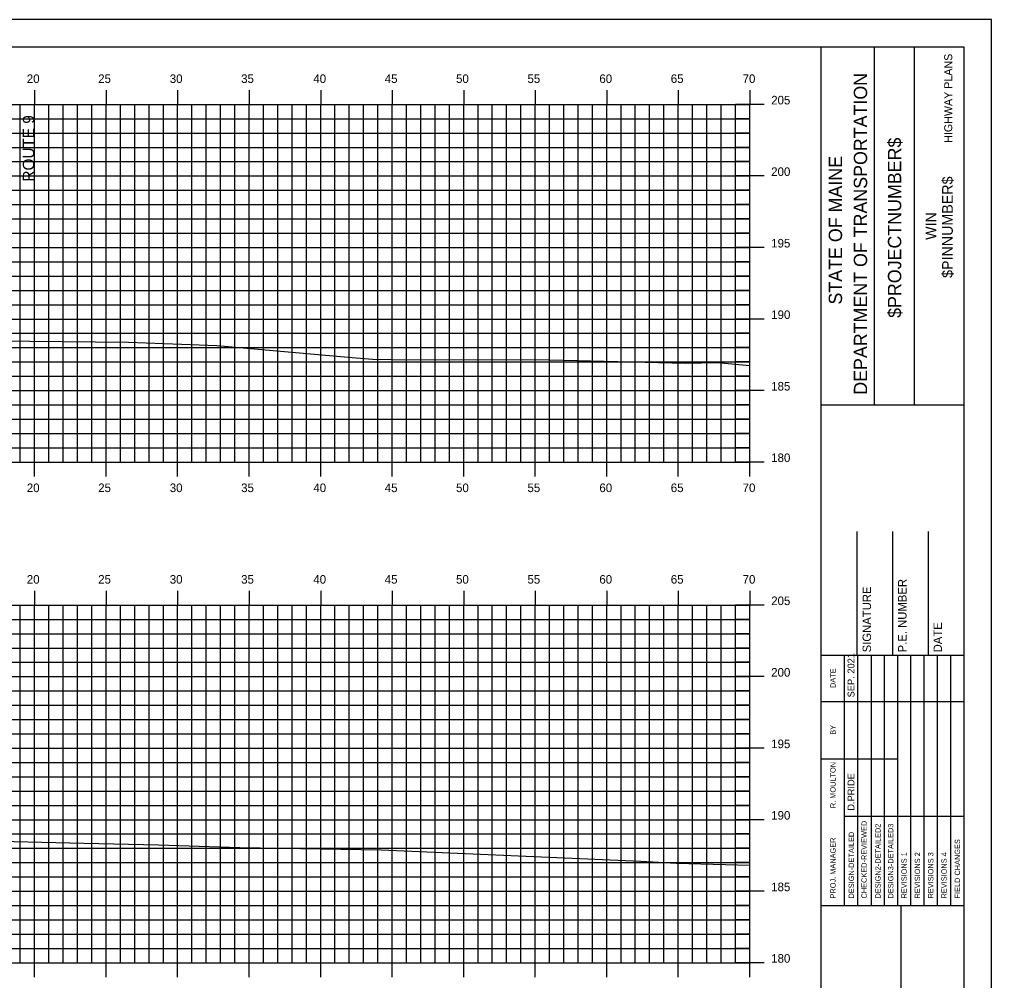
# Model space of a CAD drawing. Extents: x 1723764 to 1723936, y 458501 to 458611.
# Drawn here: x 1723866.5 to 1723934.4, y 458544 to 458611.2 of the extents above; entities that cross this region are included whole.
import ezdxf

# ---------------------------------------------------------------- set-up
doc = ezdxf.new("R2010")
doc.units = 0
for name, color, linetype in [('ANNOTATION', 7, 'Continuous'), ('BORDER', 7, 'Continuous'), ('H_V ANNOTATION', 7, 'Continuous'), ('HIGHWAY_TITLE', 7, 'Continuous'), ('MAJOR', 7, 'Continuous'), ('MINOR', 7, 'Continuous'), ('PLOT BOUNDARY', 7, 'Continuous'), ('S_Roadway_Centerline', 7, 'Continuous')]:
    doc.layers.add(name, color=color, linetype=linetype)

msp = doc.modelspace()

# ---------------------------------------------------------------- linework, layer by layer
at = {"layer": 'BORDER'}
for p, q in [((1723922.542, 458504.254), (1723922.542, 458609.254)), ((1723926.271, 458584.251), (1723926.271, 458609.251)), ((1723929.066, 458584.251), (1723929.066, 458609.251)), ((1723922.543, 458584.248), (1723932.542, 458584.248)), ((1723925.042, 458566.757), (1723925.042, 458575.405)), ((1723927.542, 458566.757), (1723927.542, 458575.405)), ((1723930.042, 458566.757), (1723930.042, 458575.405)), ((1723922.542, 458566.757), (1723932.542, 458566.757)), ((1723922.542, 458549.257), (1723932.542, 458549.257)), ((1723928.133, 458514.257), (1723928.133, 458549.257))]:
    msp.add_line(p, q, dxfattribs=at)
msp.add_lwpolyline([(1723772.542, 458504.254), (1723932.542, 458504.254), (1723932.542, 458609.254), (1723772.542, 458609.254)], close=True, dxfattribs=at)
for points in [[(1723924.157, 458563.507), (1723924.157, 458566.757)], [(1723925.09, 458549.26), (1723925.09, 458566.757)], [(1723926.021, 458566.757), (1723926.021, 458549.26)], [(1723926.953, 458549.26), (1723926.953, 458566.757)], [(1723927.885, 458549.26), (1723927.885, 458566.757)], [(1723928.816, 458549.26), (1723928.816, 458566.757)], [(1723929.748, 458549.26), (1723929.748, 458566.757)], [(1723930.68, 458549.26), (1723930.68, 458566.757)], [(1723931.611, 458549.26), (1723931.611, 458566.757)], [(1723924.158, 458549.26), (1723924.158, 458566.051)], [(1723922.542, 458563.507), (1723932.542, 458563.507)], [(1723922.542, 458559.507), (1723924.158, 458559.507)], [(1723924.157, 458559.507), (1723927.884, 458559.507)], [(1723924.157, 458555.507), (1723932.542, 458555.507)]]:
    msp.add_lwpolyline(points, dxfattribs=at)
at = {"layer": 'MAJOR'}
for p, q in [((1723867.542, 458606.256), (1723867.542, 458605.254)), ((1723872.542, 458606.256), (1723872.542, 458605.254)), ((1723877.542, 458606.256), (1723877.542, 458605.254)), ((1723882.542, 458606.256), (1723882.542, 458605.254)), ((1723887.542, 458606.256), (1723887.542, 458605.254)), ((1723892.542, 458606.256), (1723892.542, 458605.254)), ((1723897.542, 458606.256), (1723897.542, 458605.254)), ((1723902.542, 458606.256), (1723902.542, 458605.254)), ((1723907.542, 458606.256), (1723907.542, 458605.254)), ((1723912.542, 458606.256), (1723912.542, 458605.254)), ((1723917.542, 458606.256), (1723917.542, 458605.254)), ((1723777.542, 458605.254), (1723917.542, 458605.254)), ((1723777.542, 458605.254), (1723917.542, 458605.254)), ((1723867.542, 458580.254), (1723867.542, 458605.254)), ((1723872.542, 458580.254), (1723872.542, 458605.254)), ((1723877.542, 458580.254), (1723877.542, 458605.254)), ((1723882.542, 458580.254), (1723882.542, 458605.254)), ((1723887.542, 458580.254), (1723887.542, 458605.254)), ((1723892.542, 458580.254), (1723892.542, 458605.254)), ((1723897.542, 458580.254), (1723897.542, 458605.254)), ((1723902.542, 458580.254), (1723902.542, 458605.254)), ((1723907.542, 458580.254), (1723907.542, 458605.254)), ((1723912.542, 458580.254), (1723912.542, 458605.254)), ((1723918.544, 458605.254), (1723916.54, 458605.254)), ((1723917.542, 458580.254), (1723917.542, 458605.254)), ((1723917.542, 458580.254), (1723917.542, 458605.254)), ((1723777.542, 458600.254), (1723917.542, 458600.254)), ((1723918.544, 458600.254), (1723916.54, 458600.254)), ((1723777.542, 458595.254), (1723917.542, 458595.254)), ((1723918.544, 458595.254), (1723916.54, 458595.254)), ((1723777.542, 458590.254), (1723917.542, 458590.254)), ((1723918.544, 458590.254), (1723916.54, 458590.254)), ((1723777.542, 458585.254), (1723917.542, 458585.254)), ((1723918.544, 458585.254), (1723916.54, 458585.254)), ((1723777.542, 458580.254), (1723917.542, 458580.254)), ((1723777.542, 458580.254), (1723917.542, 458580.254)), ((1723867.542, 458579.252), (1723867.542, 458580.254)), ((1723872.542, 458579.252), (1723872.542, 458580.254)), ((1723877.542, 458579.252), (1723877.542, 458580.254)), ((1723882.542, 458579.252), (1723882.542, 458580.254)), ((1723887.542, 458579.252), (1723887.542, 458580.254)), ((1723892.542, 458579.252), (1723892.542, 458580.254)), ((1723897.542, 458579.252), (1723897.542, 458580.254)), ((1723902.542, 458579.252), (1723902.542, 458580.254)), ((1723907.542, 458579.252), (1723907.542, 458580.254)), ((1723912.542, 458579.252), (1723912.542, 458580.254)), ((1723918.544, 458580.254), (1723916.54, 458580.254)), ((1723917.542, 458579.252), (1723917.542, 458580.254)), ((1723867.542, 458571.256), (1723867.542, 458570.254)), ((1723872.542, 458571.256), (1723872.542, 458570.254)), ((1723877.542, 458571.256), (1723877.542, 458570.254)), ((1723882.542, 458571.256), (1723882.542, 458570.254)), ((1723887.542, 458571.256), (1723887.542, 458570.254)), ((1723892.542, 458571.256), (1723892.542, 458570.254)), ((1723897.542, 458571.256), (1723897.542, 458570.254)), ((1723902.542, 458571.256), (1723902.542, 458570.254)), ((1723907.542, 458571.256), (1723907.542, 458570.254)), ((1723912.542, 458571.256), (1723912.542, 458570.254)), ((1723917.542, 458571.256), (1723917.542, 458570.254)), ((1723777.542, 458570.254), (1723917.542, 458570.254)), ((1723777.542, 458570.254), (1723917.542, 458570.254)), ((1723867.542, 458545.254), (1723867.542, 458570.254)), ((1723872.542, 458545.254), (1723872.542, 458570.254)), ((1723877.542, 458545.254), (1723877.542, 458570.254)), ((1723882.542, 458545.254), (1723882.542, 458570.254)), ((1723887.542, 458545.254), (1723887.542, 458570.254)), ((1723892.542, 458545.254), (1723892.542, 458570.254)), ((1723897.542, 458545.254), (1723897.542, 458570.254)), ((1723902.542, 458545.254), (1723902.542, 458570.254)), ((1723907.542, 458545.254), (1723907.542, 458570.254)), ((1723912.542, 458545.254), (1723912.542, 458570.254)), ((1723918.544, 458570.254), (1723916.54, 458570.254)), ((1723917.542, 458545.254), (1723917.542, 458570.254)), ((1723917.542, 458545.254), (1723917.542, 458570.254)), ((1723777.542, 458565.254), (1723917.542, 458565.254)), ((1723918.544, 458565.254), (1723916.54, 458565.254)), ((1723777.542, 458560.254), (1723917.542, 458560.254)), ((1723918.544, 458560.254), (1723916.54, 458560.254)), ((1723777.542, 458555.254), (1723917.542, 458555.254)), ((1723918.544, 458555.254), (1723916.54, 458555.254)), ((1723777.542, 458550.254), (1723917.542, 458550.254)), ((1723918.544, 458550.254), (1723916.54, 458550.254)), ((1723777.542, 458545.254), (1723917.542, 458545.254)), ((1723777.542, 458545.254), (1723917.542, 458545.254)), ((1723867.542, 458544.252), (1723867.542, 458545.254)), ((1723872.542, 458544.252), (1723872.542, 458545.254)), ((1723877.542, 458544.252), (1723877.542, 458545.254)), ((1723882.542, 458544.252), (1723882.542, 458545.254)), ((1723887.542, 458544.252), (1723887.542, 458545.254)), ((1723892.542, 458544.252), (1723892.542, 458545.254)), ((1723897.542, 458544.252), (1723897.542, 458545.254)), ((1723902.542, 458544.252), (1723902.542, 458545.254)), ((1723907.542, 458544.252), (1723907.542, 458545.254)), ((1723912.542, 458544.252), (1723912.542, 458545.254)), ((1723918.544, 458545.254), (1723916.54, 458545.254)), ((1723917.542, 458544.252), (1723917.542, 458545.254))]:
    msp.add_line(p, q, dxfattribs=at)
at = {"layer": 'MINOR'}
for p, q in [((1723866.542, 458580.254), (1723866.542, 458605.254)), ((1723868.542, 458580.254), (1723868.542, 458605.254)), ((1723869.542, 458580.254), (1723869.542, 458605.254)), ((1723870.542, 458580.254), (1723870.542, 458605.254)), ((1723871.542, 458580.254), (1723871.542, 458605.254)), ((1723873.542, 458580.254), (1723873.542, 458605.254)), ((1723874.542, 458580.254), (1723874.542, 458605.254)), ((1723875.542, 458580.254), (1723875.542, 458605.254)), ((1723876.542, 458580.254), (1723876.542, 458605.254)), ((1723878.542, 458580.254), (1723878.542, 458605.254)), ((1723879.542, 458580.254), (1723879.542, 458605.254)), ((1723880.542, 458580.254), (1723880.542, 458605.254)), ((1723881.542, 458580.254), (1723881.542, 458605.254)), ((1723883.542, 458580.254), (1723883.542, 458605.254)), ((1723884.542, 458580.254), (1723884.542, 458605.254)), ((1723885.542, 458580.254), (1723885.542, 458605.254)), ((1723886.542, 458580.254), (1723886.542, 458605.254)), ((1723888.542, 458580.254), (1723888.542, 458605.254)), ((1723889.542, 458580.254), (1723889.542, 458605.254)), ((1723890.542, 458580.254), (1723890.542, 458605.254)), ((1723891.542, 458580.254), (1723891.542, 458605.254)), ((1723893.542, 458580.254), (1723893.542, 458605.254)), ((1723894.542, 458580.254), (1723894.542, 458605.254)), ((1723895.542, 458580.254), (1723895.542, 458605.254)), ((1723896.542, 458580.254), (1723896.542, 458605.254)), ((1723898.542, 458580.254), (1723898.542, 458605.254)), ((1723899.542, 458580.254), (1723899.542, 458605.254)), ((1723900.542, 458580.254), (1723900.542, 458605.254)), ((1723901.542, 458580.254), (1723901.542, 458605.254)), ((1723903.542, 458580.254), (1723903.542, 458605.254)), ((1723904.542, 458580.254), (1723904.542, 458605.254)), ((1723905.542, 458580.254), (1723905.542, 458605.254)), ((1723906.542, 458580.254), (1723906.542, 458605.254)), ((1723908.542, 458580.254), (1723908.542, 458605.254)), ((1723909.542, 458580.254), (1723909.542, 458605.254)), ((1723910.542, 458580.254), (1723910.542, 458605.254)), ((1723911.542, 458580.254), (1723911.542, 458605.254)), ((1723913.542, 458580.254), (1723913.542, 458605.254)), ((1723914.542, 458580.254), (1723914.542, 458605.254)), ((1723915.542, 458580.254), (1723915.542, 458605.254)), ((1723916.542, 458580.254), (1723916.542, 458605.254)), ((1723777.542, 458604.254), (1723917.542, 458604.254)), ((1723917.542, 458604.254), (1723916.54, 458604.254)), ((1723777.542, 458603.254), (1723917.542, 458603.254)), ((1723917.542, 458603.254), (1723916.54, 458603.254)), ((1723777.542, 458602.254), (1723917.542, 458602.254)), ((1723917.542, 458602.254), (1723916.54, 458602.254)), ((1723777.542, 458601.254), (1723917.542, 458601.254)), ((1723917.542, 458601.254), (1723916.54, 458601.254)), ((1723777.542, 458599.254), (1723917.542, 458599.254)), ((1723917.542, 458599.254), (1723916.54, 458599.254)), ((1723777.542, 458598.254), (1723917.542, 458598.254)), ((1723917.542, 458598.254), (1723916.54, 458598.254)), ((1723777.542, 458597.254), (1723917.542, 458597.254)), ((1723917.542, 458597.254), (1723916.54, 458597.254)), ((1723777.542, 458596.254), (1723917.542, 458596.254)), ((1723917.542, 458596.254), (1723916.54, 458596.254)), ((1723777.542, 458594.254), (1723917.542, 458594.254)), ((1723917.542, 458594.254), (1723916.54, 458594.254)), ((1723777.542, 458593.254), (1723917.542, 458593.254)), ((1723917.542, 458593.254), (1723916.54, 458593.254)), ((1723777.542, 458592.254), (1723917.542, 458592.254)), ((1723917.542, 458592.254), (1723916.54, 458592.254)), ((1723777.542, 458591.254), (1723917.542, 458591.254)), ((1723917.542, 458591.254), (1723916.54, 458591.254)), ((1723777.542, 458589.254), (1723917.542, 458589.254)), ((1723917.542, 458589.254), (1723916.54, 458589.254)), ((1723777.542, 458588.254), (1723917.542, 458588.254)), ((1723917.542, 458588.254), (1723916.54, 458588.254)), ((1723777.542, 458587.254), (1723917.542, 458587.254)), ((1723917.542, 458587.254), (1723916.54, 458587.254)), ((1723777.542, 458586.254), (1723917.542, 458586.254)), ((1723917.542, 458586.254), (1723916.54, 458586.254)), ((1723777.542, 458584.254), (1723917.542, 458584.254)), ((1723917.542, 458584.254), (1723916.54, 458584.254)), ((1723777.542, 458583.254), (1723917.542, 458583.254)), ((1723917.542, 458583.254), (1723916.54, 458583.254)), ((1723777.542, 458582.254), (1723917.542, 458582.254)), ((1723917.542, 458582.254), (1723916.54, 458582.254)), ((1723777.542, 458581.254), (1723917.542, 458581.254)), ((1723917.542, 458581.254), (1723916.54, 458581.254)), ((1723866.542, 458545.254), (1723866.542, 458570.254)), ((1723868.542, 458545.254), (1723868.542, 458570.254)), ((1723869.542, 458545.254), (1723869.542, 458570.254)), ((1723870.542, 458545.254), (1723870.542, 458570.254)), ((1723871.542, 458545.254), (1723871.542, 458570.254)), ((1723873.542, 458545.254), (1723873.542, 458570.254)), ((1723874.542, 458545.254), (1723874.542, 458570.254)), ((1723875.542, 458545.254), (1723875.542, 458570.254)), ((1723876.542, 458545.254), (1723876.542, 458570.254)), ((1723878.542, 458545.254), (1723878.542, 458570.254)), ((1723879.542, 458545.254), (1723879.542, 458570.254)), ((1723880.542, 458545.254), (1723880.542, 458570.254)), ((1723881.542, 458545.254), (1723881.542, 458570.254)), ((1723883.542, 458545.254), (1723883.542, 458570.254)), ((1723884.542, 458545.254), (1723884.542, 458570.254)), ((1723885.542, 458545.254), (1723885.542, 458570.254)), ((1723886.542, 458545.254), (1723886.542, 458570.254)), ((1723888.542, 458545.254), (1723888.542, 458570.254)), ((1723889.542, 458545.254), (1723889.542, 458570.254)), ((1723890.542, 458545.254), (1723890.542, 458570.254)), ((1723891.542, 458545.254), (1723891.542, 458570.254)), ((1723893.542, 458545.254), (1723893.542, 458570.254)), ((1723894.542, 458545.254), (1723894.542, 458570.254)), ((1723895.542, 458545.254), (1723895.542, 458570.254)), ((1723896.542, 458545.254), (1723896.542, 458570.254)), ((1723898.542, 458545.254), (1723898.542, 458570.254)), ((1723899.542, 458545.254), (1723899.542, 458570.254)), ((1723900.542, 458545.254), (1723900.542, 458570.254)), ((1723901.542, 458545.254), (1723901.542, 458570.254)), ((1723903.542, 458545.254), (1723903.542, 458570.254)), ((1723904.542, 458545.254), (1723904.542, 458570.254)), ((1723905.542, 458545.254), (1723905.542, 458570.254)), ((1723906.542, 458545.254), (1723906.542, 458570.254)), ((1723908.542, 458545.254), (1723908.542, 458570.254)), ((1723909.542, 458545.254), (1723909.542, 458570.254)), ((1723910.542, 458545.254), (1723910.542, 458570.254)), ((1723911.542, 458545.254), (1723911.542, 458570.254)), ((1723913.542, 458545.254), (1723913.542, 458570.254)), ((1723914.542, 458545.254), (1723914.542, 458570.254)), ((1723915.542, 458545.254), (1723915.542, 458570.254)), ((1723916.542, 458545.254), (1723916.542, 458570.254)), ((1723777.542, 458569.254), (1723917.542, 458569.254)), ((1723917.542, 458569.254), (1723916.54, 458569.254)), ((1723777.542, 458568.254), (1723917.542, 458568.254)), ((1723917.542, 458568.254), (1723916.54, 458568.254)), ((1723777.542, 458567.254), (1723917.542, 458567.254)), ((1723917.542, 458567.254), (1723916.54, 458567.254)), ((1723777.542, 458566.254), (1723917.542, 458566.254)), ((1723917.542, 458566.254), (1723916.54, 458566.254)), ((1723777.542, 458564.254), (1723917.542, 458564.254)), ((1723917.542, 458564.254), (1723916.54, 458564.254)), ((1723777.542, 458563.254), (1723917.542, 458563.254)), ((1723917.542, 458563.254), (1723916.54, 458563.254)), ((1723777.542, 458562.254), (1723917.542, 458562.254)), ((1723917.542, 458562.254), (1723916.54, 458562.254)), ((1723777.542, 458561.254), (1723917.542, 458561.254)), ((1723917.542, 458561.254), (1723916.54, 458561.254)), ((1723777.542, 458559.254), (1723917.542, 458559.254)), ((1723917.542, 458559.254), (1723916.54, 458559.254)), ((1723777.542, 458558.254), (1723917.542, 458558.254)), ((1723917.542, 458558.254), (1723916.54, 458558.254)), ((1723777.542, 458557.254), (1723917.542, 458557.254)), ((1723917.542, 458557.254), (1723916.54, 458557.254)), ((1723777.542, 458556.254), (1723917.542, 458556.254)), ((1723917.542, 458556.254), (1723916.54, 458556.254)), ((1723777.542, 458554.254), (1723917.542, 458554.254)), ((1723917.542, 458554.254), (1723916.54, 458554.254)), ((1723777.542, 458553.254), (1723917.542, 458553.254)), ((1723917.542, 458553.254), (1723916.54, 458553.254)), ((1723777.542, 458552.254), (1723917.542, 458552.254)), ((1723917.542, 458552.254), (1723916.54, 458552.254)), ((1723777.542, 458551.254), (1723917.542, 458551.254)), ((1723917.542, 458551.254), (1723916.54, 458551.254)), ((1723777.542, 458549.254), (1723917.542, 458549.254)), ((1723917.542, 458549.254), (1723916.54, 458549.254)), ((1723777.542, 458548.254), (1723917.542, 458548.254)), ((1723917.542, 458548.254), (1723916.54, 458548.254)), ((1723777.542, 458547.254), (1723917.542, 458547.254)), ((1723917.542, 458547.254), (1723916.54, 458547.254)), ((1723777.542, 458546.254), (1723917.542, 458546.254)), ((1723917.542, 458546.254), (1723916.54, 458546.254))]:
    msp.add_line(p, q, dxfattribs=at)
at = {"layer": 'PLOT BOUNDARY'}
msp.add_lwpolyline([(1723764.449, 458501.195), (1723934.449, 458501.195), (1723934.449, 458611.195), (1723764.449, 458611.195)], close=True, dxfattribs=at)
at = {"layer": 'S_Roadway_Centerline'}
for points in [[(1723777.542, 458590.535), (1723782.572, 458590.478), (1723794.565, 458590.362), (1723795.815, 458590.342), (1723798.304, 458590.194), (1723814.321, 458589.653), (1723828.082, 458589.474), (1723834.118, 458589.453), (1723843.37, 458589.361), (1723853.307, 458588.898), (1723862.561, 458588.74), (1723874.103, 458588.626), (1723880.292, 458588.403), (1723889.466, 458587.592), (1723891.167, 458587.447), (1723892.536, 458587.426), (1723903.57, 458587.401), (1723913.068, 458587.172), (1723915.267, 458587.202), (1723917.542, 458586.995)], [(1723777.542, 458555.901), (1723777.899, 458555.886), (1723781.729, 458555.712), (1723784.914, 458555.809), (1723792.946, 458556.04), (1723804.299, 458555.71), (1723805.143, 458555.656), (1723805.732, 458555.623), (1723817.844, 458555.138), (1723827.379, 458554.731), (1723828.288, 458554.733), (1723838.5, 458554.836), (1723849.73, 458554.584), (1723856.129, 458554.317), (1723863.147, 458553.81), (1723870.978, 458553.613), (1723876.204, 458553.497), (1723881.901, 458553.314), (1723891.771, 458553.149), (1723909.916, 458552.356), (1723912.425, 458552.215), (1723917.542, 458552.075)]]:
    msp.add_lwpolyline(points, dxfattribs=at)

# ---------------------------------------------------------------- texts
at = {"layer": 'ANNOTATION'}
msp.add_text('ROUTE 9', height=0.8, rotation=90, dxfattribs=at).set_placement((1723867.516, 458599.864))
at = {"layer": 'BORDER'}
for s, height, p in [('DEPARTMENT OF TRANSPORTATION', 0.93176, (1723925.749, 458584.96)), ('$PROJECTNUMBER$', 0.93176, (1723928.134, 458590.333)), ('STATE OF MAINE', 0.93176, (1723923.997, 458591.266)), ('$PINNUMBER$', 0.74527, (1723931.738, 458593.129)), ('WIN', 0.7453, (1723930.579, 458595.784)), ('P.E. NUMBER', 0.59055, (1723928.503, 458566.949)), ('SIGNATURE', 0.5906, (1723926.023, 458566.949)), ('DATE', 0.5906, (1723930.983, 458566.949)), ('SEP. 2021', 0.4845, (1723924.865, 458563.803)), ('DATE', 0.3714, (1723923.546, 458564.463)), ('BY', 0.3714, (1723923.546, 458561.192)), ('R. MOULTON', 0.3727, (1723923.546, 458556.06)), ('D.PRIDE', 0.4845, (1723924.865, 458555.88)), ('CHECKED-REVIEWED', 0.37275, (1723925.723, 458549.745)), ('DESIGN-DETAILED', 0.37275, (1723924.829, 458549.745)), ('DESIGN2-DETAILED2', 0.37275, (1723926.692, 458549.745)), ('DESIGN3-DETAILED3', 0.37275, (1723927.586, 458549.745)), ('PROJ. MANAGER', 0.37275, (1723923.546, 458549.745)), ('FIELD CHANGES', 0.37275, (1723932.245, 458549.745)), ('REVISIONS 1', 0.37275, (1723928.518, 458549.745)), ('REVISIONS 2', 0.37275, (1723929.45, 458549.745)), ('REVISIONS 3', 0.37275, (1723930.382, 458549.745)), ('REVISIONS 4', 0.37275, (1723931.313, 458549.745))]:
    msp.add_text(s, height=height, rotation=90, dxfattribs=at).set_placement(p)
at = {"layer": 'H_V ANNOTATION'}
for s, p in [('20', (1723866.996, 458606.754)), ('25', (1723871.988, 458606.754)), ('30', (1723876.991, 458606.754)), ('35', (1723881.983, 458606.754)), ('40', (1723887.028, 458606.754)), ('45', (1723892.02, 458606.754)), ('50', (1723897.007, 458606.754)), ('55', (1723901.999, 458606.754)), ('60', (1723907.028, 458606.754)), ('65', (1723912.02, 458606.754)), ('70', (1723917.044, 458606.754)), ('205', (1723919.042, 458605.254)), ('200', (1723919.042, 458600.254)), ('195', (1723919.042, 458595.254)), ('190', (1723919.042, 458590.254)), ('185', (1723919.042, 458585.254)), ('180', (1723919.042, 458580.254)), ('20', (1723866.996, 458578.154)), ('25', (1723871.988, 458578.154)), ('30', (1723876.991, 458578.154)), ('35', (1723881.983, 458578.154)), ('40', (1723887.028, 458578.154)), ('45', (1723892.02, 458578.154)), ('50', (1723897.007, 458578.154)), ('55', (1723901.999, 458578.154)), ('60', (1723907.028, 458578.154)), ('65', (1723912.02, 458578.154)), ('70', (1723917.044, 458578.154)), ('20', (1723866.996, 458571.754)), ('25', (1723871.988, 458571.754)), ('30', (1723876.991, 458571.754)), ('35', (1723881.983, 458571.754)), ('40', (1723887.028, 458571.754)), ('45', (1723892.02, 458571.754)), ('50', (1723897.007, 458571.754)), ('55', (1723901.999, 458571.754)), ('60', (1723907.028, 458571.754)), ('65', (1723912.02, 458571.754)), ('70', (1723917.044, 458571.754)), ('205', (1723919.042, 458570.254)), ('200', (1723919.042, 458565.254)), ('195', (1723919.042, 458560.254)), ('190', (1723919.042, 458555.254)), ('185', (1723919.042, 458550.254)), ('180', (1723919.042, 458545.254))]:
    msp.add_text(s, height=0.6, dxfattribs=at).set_placement(p)
at = {"layer": 'HIGHWAY_TITLE'}
msp.add_text('HIGHWAY PLANS', height=0.55901, rotation=90, dxfattribs=at).set_placement((1723931.7, 458602.57))

doc.saveas('drawing.dxf')
